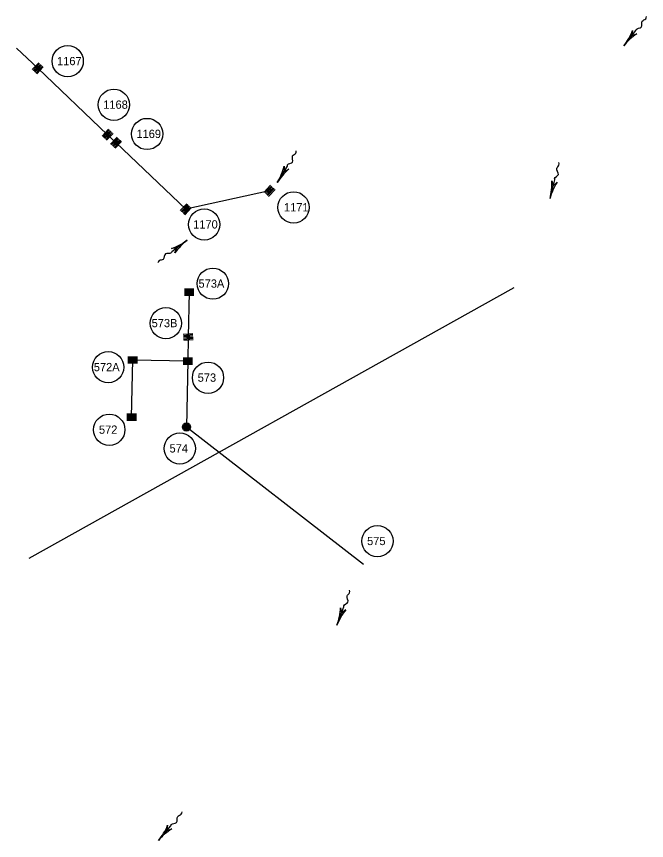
# Model space of a CAD drawing. Extents: x 594534 to 598564, y 225861 to 236229.
# Drawn here: x 596864 to 597321, y 230734 to 231332 of the extents above; entities that cross this region are included whole.
import ezdxf

# ---------------------------------------------------------------- set-up
doc = ezdxf.new("R2010")
doc.units = 0
for name, color, linetype in [('P_DRN_Flow', 7, 'Continuous'), ('P_DRN_Inlet', 7, 'Continuous'), ('P_DRN_Pipes', 7, 'Continuous'), ('P_DRN_SS_MH', 7, 'Continuous'), ('P_DRN_SS_UG', 7, 'Continuous'), ('P_DRN_Text', 7, 'Continuous')]:
    doc.layers.add(name, color=color, linetype=linetype)

msp = doc.modelspace()

# ---------------------------------------------------------------- linework, layer by layer
at = {"layer": 'P_DRN_Flow'}
for p, q in [((597304.69, 231310.72), (597313.49, 231321.78)), ((597052.98, 231211.36), (597060.37, 231223.4)), ((597251.18, 231199.74), (597254.64, 231213.44)), ((596987.64, 231169.57), (596976.32, 231161.11)), ((597096.39, 230889.91), (597101.34, 230903.14)), ((596966.63, 230733.52), (596975.75, 230744.3))]:
    msp.add_line(p, q, dxfattribs=at)
for points in [[(597311.09, 231321.98), (597310.67, 231318.23), (597314.23, 231319.5)], [(597057.96, 231223.31), (597058, 231219.54), (597061.38, 231221.22)], [(597252.37, 231212.64), (597253.53, 231209.05), (597256.25, 231211.66)], [(596978.59, 231160.31), (596979.96, 231163.83), (596976.19, 231163.51)], [(597099, 230902.6), (597099.75, 230898.9), (597102.75, 230901.2)], [(596973.36, 230744.58), (596972.82, 230740.85), (596976.42, 230742)]]:
    msp.add_lwpolyline(points, dxfattribs=at)
for centre, start, end in [((597271.86, 231336.85), 321.48295, 339.24527), ((597337.52, 231284.6), 123.72063, 141.48295), ((597017.22, 231233.31), 328.46048, 346.2228), ((597088.74, 231189.41), 130.69816, 148.46048), ((597210.5, 231210), 345.84076, 3.60308), ((597291.86, 231189.48), 148.07844, 165.84076), ((596962.52, 231203.18), 289.01642, 306.77874), ((597012.76, 231135.97), 126.77874, 144.54106), ((597057.1, 230904.63), 339.46477, 357.22709), ((597135.68, 230875.19), 141.70245, 159.46477), ((596934.6, 230760.62), 319.76021, 337.52253), ((596998.65, 230706.42), 121.99789, 139.76021)]:
    msp.add_arc(centre, 41.96, start, end, dxfattribs=at)
for points in [[(597313.49, 231321.78), (597313.73, 231322.59), (597317.46, 231324.24), (597318.18, 231328.68), (597320.68, 231330.3), (597321.26, 231332.05)], [(597060.37, 231223.4), (597060.51, 231224.23), (597064, 231226.33), (597064.19, 231230.82), (597066.47, 231232.74), (597066.83, 231234.54)], [(597254.64, 231213.44), (597254.52, 231214.28), (597257.23, 231217.32), (597256.06, 231221.66), (597257.67, 231224.17), (597257.48, 231226)], [(596976.32, 231161.11), (596975.88, 231160.39), (596971.86, 231159.74), (596970.04, 231155.63), (596967.21, 231154.69), (596966.2, 231153.16)], [(597101.34, 230903.14), (597101.33, 230903.99), (597104.36, 230906.71), (597103.68, 230911.15), (597105.55, 230913.47), (597105.57, 230915.31)], [(596975.75, 230744.3), (596976.02, 230745.11), (596979.79, 230746.65), (596980.65, 230751.06), (596983.19, 230752.61), (596983.83, 230754.33)]]:
    msp.add_spline(points, degree=3, dxfattribs=at)
at = {"layer": 'P_DRN_Inlet'}
for p, q in [((596875.02, 231293.45), (596879.73, 231298.46)), ((596875.68, 231292.83), (596880.39, 231297.84)), ((596876.33, 231292.22), (596881.04, 231297.23)), ((596876.99, 231291.6), (596881.7, 231296.61)), ((596877.64, 231290.99), (596882.35, 231296)), ((596878.3, 231290.37), (596883.01, 231295.38)), ((596925.76, 231245.23), (596930.47, 231250.24)), ((596926.42, 231244.61), (596931.12, 231249.62)), ((596927.07, 231243.99), (596931.78, 231249)), ((596927.73, 231243.38), (596932.44, 231248.39)), ((596928.38, 231242.76), (596933.09, 231247.77)), ((596929.04, 231242.14), (596933.75, 231247.15)), ((596931.91, 231239.36), (596936.62, 231244.37)), ((596932.57, 231238.74), (596937.27, 231243.75)), ((596933.22, 231238.13), (596937.93, 231243.14)), ((596933.88, 231237.51), (596938.59, 231242.52)), ((596934.53, 231236.89), (596939.24, 231241.9)), ((596935.19, 231236.28), (596939.9, 231241.29)), ((597043.39, 231204.46), (597048.1, 231209.47)), ((597044.04, 231203.85), (597048.75, 231208.86)), ((597044.7, 231203.23), (597049.41, 231208.24)), ((597045.36, 231202.61), (597050.06, 231207.62)), ((597046.01, 231202), (597050.72, 231207.01)), ((597046.67, 231201.38), (597051.38, 231206.39)), ((596982.56, 231191.04), (596987.27, 231196.05)), ((596983.22, 231190.43), (596987.92, 231195.44)), ((596983.87, 231189.81), (596988.58, 231194.82)), ((596984.53, 231189.19), (596989.24, 231194.2)), ((596985.18, 231188.58), (596989.89, 231193.59)), ((596985.84, 231187.96), (596990.55, 231192.97)), ((596985.52, 231134.11), (596992.39, 231134.11)), ((596985.52, 231133.21), (596992.39, 231133.21)), ((596985.52, 231132.31), (596992.39, 231132.31)), ((596985.52, 231131.41), (596992.39, 231131.41)), ((596985.52, 231130.51), (596992.39, 231130.51)), ((596985.52, 231129.61), (596992.39, 231129.61)), ((596984.72, 231101.34), (596991.58, 231101.88)), ((596984.79, 231100.44), (596991.65, 231100.98)), ((596984.86, 231099.55), (596991.72, 231100.09)), ((596984.93, 231098.65), (596991.79, 231099.19)), ((596985, 231097.75), (596991.86, 231098.29)), ((596985.07, 231096.85), (596991.93, 231097.39)), ((596944.55, 231084.89), (596951.43, 231084.89)), ((596944.55, 231083.99), (596951.43, 231083.99)), ((596944.55, 231083.09), (596951.43, 231083.09)), ((596944.55, 231082.19), (596951.43, 231082.19)), ((596944.55, 231081.29), (596951.43, 231081.29)), ((596944.55, 231080.39), (596951.43, 231080.39)), ((596984.55, 231084.12), (596991.42, 231084.12)), ((596984.55, 231083.22), (596991.42, 231083.22)), ((596984.55, 231082.32), (596991.42, 231082.32)), ((596984.55, 231081.42), (596991.42, 231081.42)), ((596984.55, 231080.52), (596991.42, 231080.52)), ((596984.55, 231079.62), (596991.42, 231079.62)), ((596943.75, 231043.37), (596950.62, 231043.37)), ((596943.75, 231042.47), (596950.62, 231042.47)), ((596943.75, 231041.57), (596950.62, 231041.57)), ((596943.75, 231040.67), (596950.62, 231040.67)), ((596943.75, 231039.77), (596950.62, 231039.77)), ((596943.75, 231038.87), (596950.62, 231038.87))]:
    msp.add_line(p, q, dxfattribs=at)
for points in [[(596879.06, 231293), (596880.43, 231294.46), (596878.97, 231295.83), (596877.6, 231294.37)], [(596929.8, 231244.78), (596931.17, 231246.23), (596929.71, 231247.6), (596928.34, 231246.15)], [(596935.95, 231238.91), (596937.32, 231240.37), (596935.86, 231241.74), (596934.49, 231240.28)], [(597047.43, 231204.01), (597048.8, 231205.47), (597047.34, 231206.84), (597045.97, 231205.38)], [(596986.6, 231190.59), (596987.97, 231192.05), (596986.51, 231193.42), (596985.14, 231191.96)], [(596987.96, 231130.86), (596989.96, 231130.86), (596989.96, 231132.86), (596987.96, 231132.86)], [(596987.41, 231098.29), (596989.4, 231098.45), (596989.24, 231100.44), (596987.25, 231100.29)], [(596946.99, 231081.64), (596948.99, 231081.64), (596948.99, 231083.64), (596946.99, 231083.64)], [(596986.98, 231080.87), (596988.98, 231080.87), (596988.98, 231082.87), (596986.98, 231082.87)], [(596946.18, 231040.12), (596948.18, 231040.12), (596948.18, 231042.12), (596946.18, 231042.12)]]:
    msp.add_lwpolyline(points, close=True, dxfattribs=at)
at = {"layer": 'P_DRN_Pipes'}
msp.add_line((597224.79, 231134.98), (596872.59, 230938.35), dxfattribs=at)
at = {"layer": 'P_DRN_SS_MH'}
for radius in [2.98, 2.4, 1.8, 1.2, 0.6]:
    msp.add_circle((596987.05, 231033.88), radius, dxfattribs=at)
at = {"layer": 'P_DRN_SS_UG'}
for p, q in [((596879.01, 231294.42), (596863.54, 231309.13)), ((597047.38, 231205.43), (596986.55, 231192.01)), ((596988.96, 231131.86), (596988.33, 231099.37)), ((596988.33, 231099.37), (596987.98, 231081.87)), ((596947.18, 231041.12), (596947.99, 231082.64)), ((596947.99, 231082.64), (596987.98, 231081.87)), ((596987.98, 231081.87), (596987.05, 231033.88)), ((596987.05, 231033.88), (597115.67, 230934.34))]:
    msp.add_line(p, q, dxfattribs=at)
for points in [[(596929.75, 231246.19), (596879.01, 231294.42)], [(596935.9, 231240.32), (596929.75, 231246.19)], [(596986.55, 231192.01), (596935.9, 231240.32)]]:
    msp.add_lwpolyline(points, dxfattribs=at)
at = {"layer": 'P_DRN_Text'}
for centre in [(596900.75, 231299.58), (596934.31, 231267.94), (596958.43, 231246.7), (597064.86, 231193.38), (596999.92, 231180.96), (597006.24, 231137.98), (596972.08, 231109.27), (596930.17, 231077.31), (597002.69, 231069.65), (596930.95, 231031.88), (596982.22, 231018.26), (597125.76, 230951)]:
    msp.add_circle(centre, 11.36, dxfattribs=at)

# ---------------------------------------------------------------- texts
for s, p in [('1167', (596893.01, 231296.66)), ('1168', (596926.58, 231265.02)), ('1169', (596950.7, 231243.78)), ('1171', (597057.88, 231190.46)), ('1170', (596991.92, 231178.04)), ('573A', (596995.79, 231135.06)), ('573B', (596961.73, 231106.35)), ('572A', (596919.72, 231074.39)), ('573', (596995.19, 231066.74)), ('572', (596923.45, 231028.96)), ('574', (596974.73, 231015.34)), ('575', (597118.26, 230948.08))]:
    msp.add_text(s, height=6, dxfattribs=at).set_placement(p)

doc.saveas('drawing.dxf')
